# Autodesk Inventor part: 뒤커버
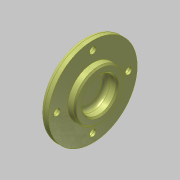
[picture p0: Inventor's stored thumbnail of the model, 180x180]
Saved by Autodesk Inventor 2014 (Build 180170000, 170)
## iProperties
Created: 2015-12
Part Number: 뒤커버
Document SubType Name: Modeling
Designer: mdu
Density: 2.71 g/cm^3
Material: 알루미늄 6061
Mass: 56.2007 g
Surface Area: 84.0408 cm^2
Volume: 20.7383 cm^3
Appearance: 알루미늄 - 평지
Author: mdu
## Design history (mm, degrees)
sketch "스케치1"
  geometry: L1 (-7, 0)-(7, 0); L2 (-7, 0)-(-7, 15.539); L3 (-7, 15.539)-(-4, 18.5); L4 (-4, 18.5)-(-4, 31); L5 (-4, 31)-(2, 31); L6 (2, 31)-(2, 17.5); L7 (2, 17.5)-(7, 17.5); L8 (7, 17.5)-(7, 0); 2 further points
  constraints: 16 end point, 4 parallel, 2 perpendicular, 1 coincident, 1 horizontal, 1 midpoint
  dimensions: "d0" = 14 distance of L1.start L1.end; "d1" = 62 diameter of L5 L1; "d2" = 35 diameter of L7 L1; "d3" = 37 diameter of L3.end L1; "d4" = 3 distance between parallel lines of L4 L2; "d5" = 6 distance of L4.end L5.end
revolve "회전1" sketch "스케치1" stored, may be unused: angle "d6" = 90 deg
sketch "스케치2" dims "d32" = 50
  geometry: 3 further points
  constraints: 2 vertical alignment, 1 coincident, 2 other
hole "구멍1" sketch "스케치2" at (0, 25) diameter "d8" = 4.5; stored, may be unused: countersink angle "d12" = 90 deg, drill point angle "d14" = 118 deg; dims "d9" = 6, "d10" = 8, "d11" = 4.4, "d13" = 8
hole "구멍2" diameter "d20" = 24; stored, may be unused: countersink angle "d24" = 90 deg, drill point angle "d26" = 0 deg; dims "d18" = 10, "d19" = 10, "d21" = 6, "d22" = 8, "d23" = 4.4, "d25" = 8
fillet "모깎기1" dims "d27" = 3
fillet "모깎기2" dims "d28" = 3
chamfer "모따기1" distance "d29" = 1; stored, may be unused: second distance "d30" = 2, angle "d31" = 45 deg
node "솔리드1"
pattern_circular "원형 패턴1" dims angle "d16" = 360 deg
